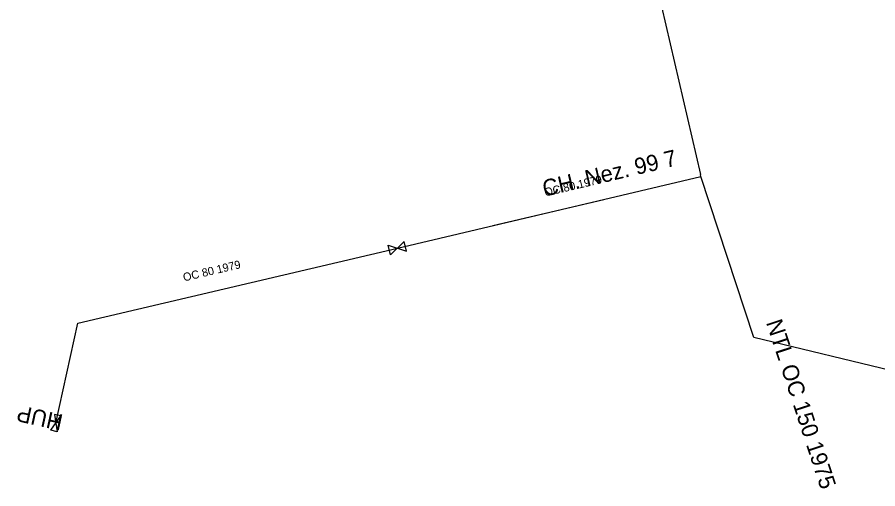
# Model space of a CAD drawing. Extents: x -743325 to -742825, y -1051501 to -1050981.
# Drawn here: x -743111.6 to -743058.8, y -1051276.6 to -1051247.7 of the extents above; entities that cross this region are included whole.
import ezdxf

# ---------------------------------------------------------------- set-up
doc = ezdxf.new("R2010")
doc.units = 0
for name, color, linetype in [('NT OP Chráni_ka - provoz', 7, 'Continuous'), ('NT Úsek p_ípojky - provoz', 7, 'Continuous'), ('NT Úsek plynovodu - provoz', 7, 'Continuous'), ('NT_HUP_24_popis', 7, 'Continuous'), ('Vrstva 1', 7, 'Continuous')]:
    doc.layers.add(name, color=color, linetype=linetype)

msp = doc.modelspace()

# ---------------------------------------------------------------- linework, layer by layer
at = {"layer": 'NT OP Chráni_ka - provoz'}
msp.add_lwpolyline([(-743082.386, -1051260.488), (-743075.573, -1051258.881)], dxfattribs=at)
at = {"layer": 'NT Úsek p_ípojky - provoz'}
for points in [[(-743088.24, -1051261.868), (-743069.623, -1051257.478)], [(-743109.184, -1051272.604), (-743107.835, -1051266.473), (-743088.24, -1051261.868)]]:
    msp.add_lwpolyline(points, dxfattribs=at)
at = {"layer": 'NT Úsek plynovodu - provoz'}
for points in [[(-743070.968, -1051164.821), (-743071.535, -1051165.016), (-743070.085, -1051169.589), (-743067.096, -1051178.869), (-743066.357, -1051181.989), (-743073.395, -1051209.661), (-743074.036, -1051212.311), (-743075.117, -1051219.935), (-743074.627, -1051228.857), (-743073.099, -1051242.438), (-743069.652, -1051257.351)], [(-743057.412, -1051269.531), (-743066.388, -1051267.351), (-743069.623, -1051257.478), (-743069.652, -1051257.351)]]:
    msp.add_lwpolyline(points, dxfattribs=at)
at = {"layer": 'Vrstva 1'}
for p, q in [((-743087.82, -1051261.463), (-743088.66, -1051262.273)), ((-743087.685, -1051262.048), (-743087.82, -1051261.463)), ((-743088.66, -1051262.273), (-743088.795, -1051261.688)), ((-743088.795, -1051261.688), (-743087.685, -1051262.048))]:
    msp.add_line(p, q, dxfattribs=at)
msp.add_lwpolyline([(-743109.096, -1051273.135), (-743109.487, -1051273.049), (-743108.881, -1051272.159), (-743109.272, -1051272.073), (-743109.096, -1051273.135)], dxfattribs=at)

# ---------------------------------------------------------------- texts
at = {"layer": 'NT OP Chráni_ka - provoz'}
msp.add_text('CH. Nez. 99 7', height=1, rotation=13.2719, dxfattribs=at).set_placement((-743079.209, -1051258.711))
at = {"layer": 'NT Úsek p_ípojky - provoz'}
for rotation, p in [(13.2683, (-743079.161, -1051258.7)), (13.225, (-743101.322, -1051263.915))]:
    msp.add_text('OC 80 1979', height=0.5, rotation=rotation, dxfattribs=at).set_placement(p)
at = {"layer": 'NT Úsek plynovodu - provoz'}
msp.add_text('NTL OC 150 1975', height=1, rotation=288.142, dxfattribs=at).set_placement((-743065.637, -1051266.43))
at = {"layer": 'NT_HUP_24_popis'}
msp.add_text('HUP', height=1, rotation=167.59, dxfattribs=at).set_placement((-743108.684, -1051272.104))

doc.saveas('drawing.dxf')
